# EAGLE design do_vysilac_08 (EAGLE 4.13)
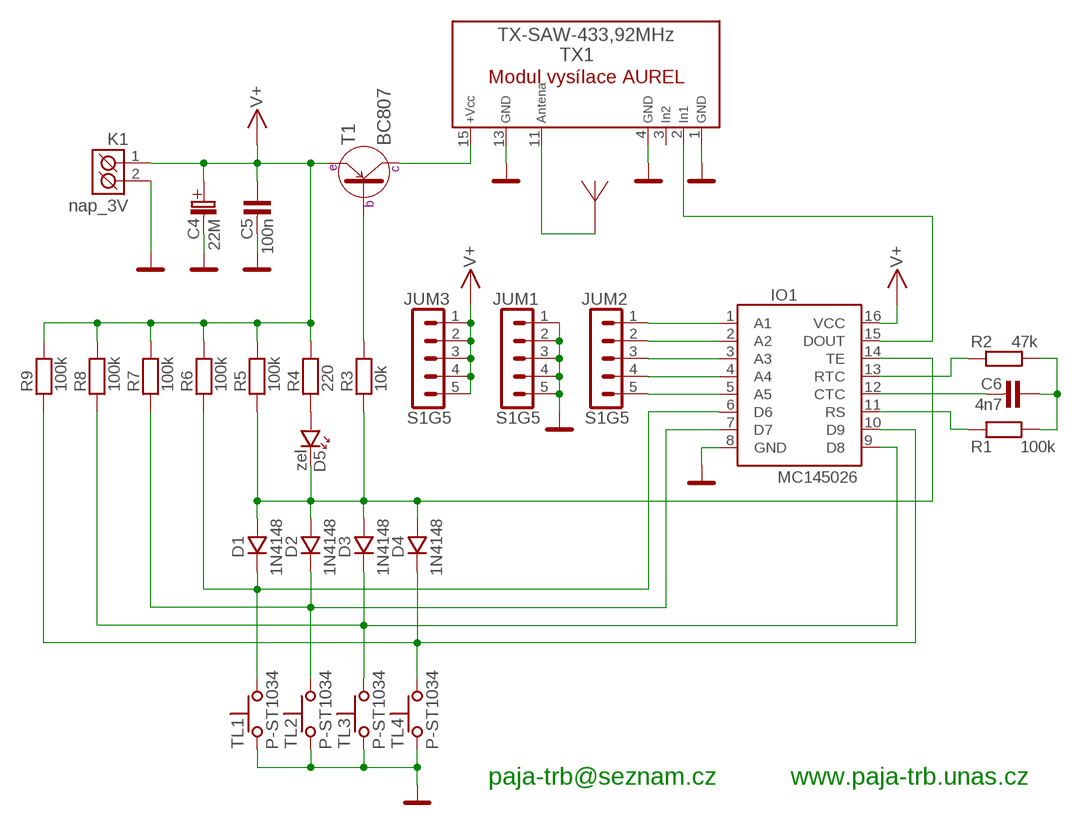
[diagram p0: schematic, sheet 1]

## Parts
ANT1  ANTENA  [PAD_1]
C4  22M  C-ELEKTROLYT_2  [C-EL_2]
C5  100n  C-KERAMIK_SMD_1206  [1206]
C6  4n7  C-KERAMIK_SMD_1206  [1206]
D1  1N4148  1N4148_SMD_SOD80  [SOD-80]
D2  1N4148  1N4148_SMD_SOD80  [SOD-80]
D3  1N4148  1N4148_SMD_SOD80  [SOD-80]
D4  1N4148  1N4148_SMD_SOD80  [SOD-80]
D5  zel  LED_3  [LED_3]
IO1  MC145026  [DIL16]
JUM1  S1G5  S1G5_JUMP  [S1G5_JUM]
JUM2  S1G5  S1G5_JUMP  [S1G5_JUM]
JUM3  S1G5  S1G5_JUMP  [S1G5_JUM]
K1  nap_3V  CZM_5/2  [CZM_5/2]
R1  100k  R_SMD_1206  [1206]
R2  47k  R_SMD_1206  [1206]
R3  10k  R_SMD_1206  [1206]
R4  220  R_SMD_1206  [1206]
R5  100k  R_SMD_1206  [1206]
R6  100k  R_SMD_1206  [1206]
R7  100k  R_SMD_1206  [1206]
R8  100k  R_SMD_1206  [1206]
R9  100k  R_SMD_1206  [1206]
T1  BC807  [SOT-23]
TL1  P-ST1034  [P-ST1034]
TL2  P-ST1034  [P-ST1034]
TL3  P-ST1034  [P-ST1034]
TL4  P-ST1034  [P-ST1034]
TX1  TX-SAW433  [TX-SAW]

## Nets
+3V: C4.C+(C_EL+) C5.1 IO1.16(VCC) JUM3.1 JUM3.2 JUM3.3 JUM3.4 JUM3.5 K1.1(K1) R4.2 R5.2 R6.2 R7.2 R8.2 R9.2 T1.1(E) ; supply symbol labelled V+
GND: C4.C-(C_EL-) C5.2 IO1.8(GND) JUM1.1 JUM1.2 JUM1.3 JUM1.4 JUM1.5 K1.2(K2) TL1.S TL2.S TL3.S TL4.S TX1.1(GND) TX1.4(GND) TX1.13(GND)
N$1: IO1.11(RS) R1.1
N$3: D2.K IO1.7(D7) R7.1 TL2.1
N$4: D5.A R4.1
N$5: IO1.1(A1) JUM2.1
N$6: D1.K IO1.6(D6) R6.1 TL1.1
N$7: D1.A D2.A D3.A D4.A D5.K IO1.14(TE) R3.1 R5.1
N$8: IO1.15(DOUT) TX1.2(IN1)
N$9: IO1.13(RTC) R2.1
N$10: C6.2 IO1.12(CTC)
N$11: C6.1 R1.2 R2.2
N$12: D4.K IO1.10(D9) R9.1 TL4.1
N$13: D3.K IO1.9(D8) R8.1 TL3.1
N$14: R3.2 T1.2(B)
N$15: T1.3(C) TX1.15(VCC)
N$21: IO1.2(A2) JUM2.2
N$22: IO1.3(A3) JUM2.3
N$23: IO1.4(A4) JUM2.4
N$24: IO1.5(A5) JUM2.5
N$25: ANT1.1 TX1.11(ANTENA)
Unconnected: TX1.3(IN2)

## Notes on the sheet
- paja-trb@seznam.cz | www.paja-trb.unas.cz

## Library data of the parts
ANT1 = #PaJa_15:ANTENA: SCH symbol - Anteny + pajeci bod na DPS
C4 = #PaJa_15:C-ELEKTROLYT: Kondenzator - elektrolyticky
C5 C6 = #PaJa_15:C-KERAMIK: Kondenzator - keramicky
D1-D4 = #PaJa_15:1N4148: Univerzalni dioda - 0,15A, 75V
D5 = #PaJa_15:LED: LED - jednobarevna
IO1 = #PaJa_15:MC145026
JUM1-JUM3 = #PaJa_15:S1G5_JUMP: Radove konektory - koliky - 5x
K1 = #PaJa_15:CZM_5/2: Svorkovnice - roztec 5,08mm - dvojita
R1-R9 = #PaJa_15:R: Rezistor
T1 = #PaJa_15:BC807
TL1-TL4 = #PaJa_19:P-ST1034: &micro;-spinac - (10x10mm)
TX1 = #PaJa_15:TX-SAW433

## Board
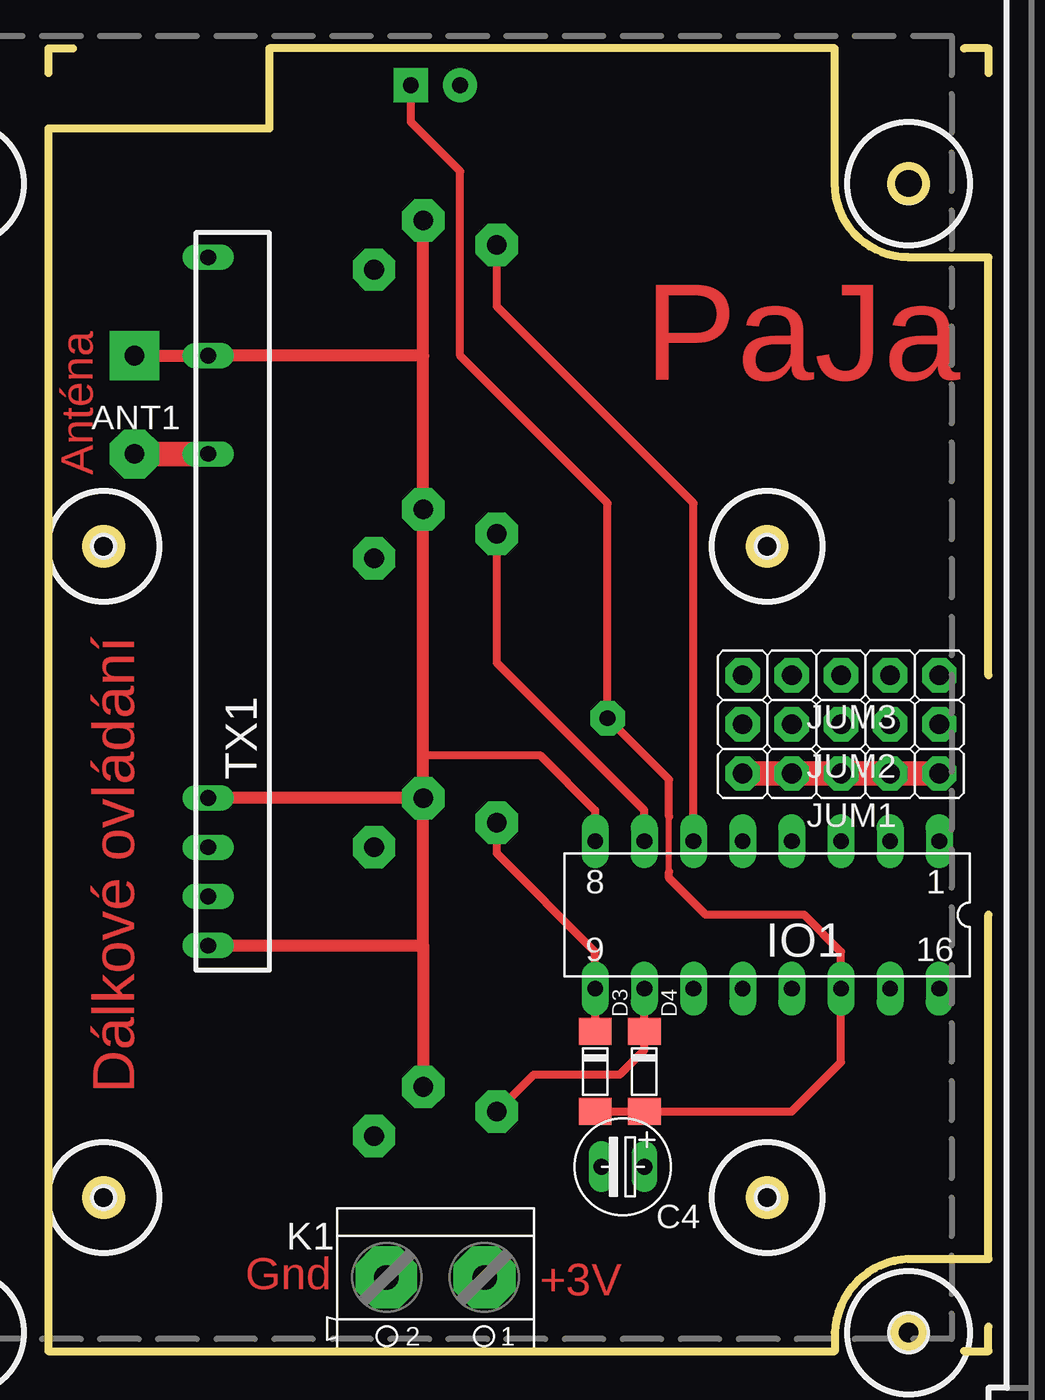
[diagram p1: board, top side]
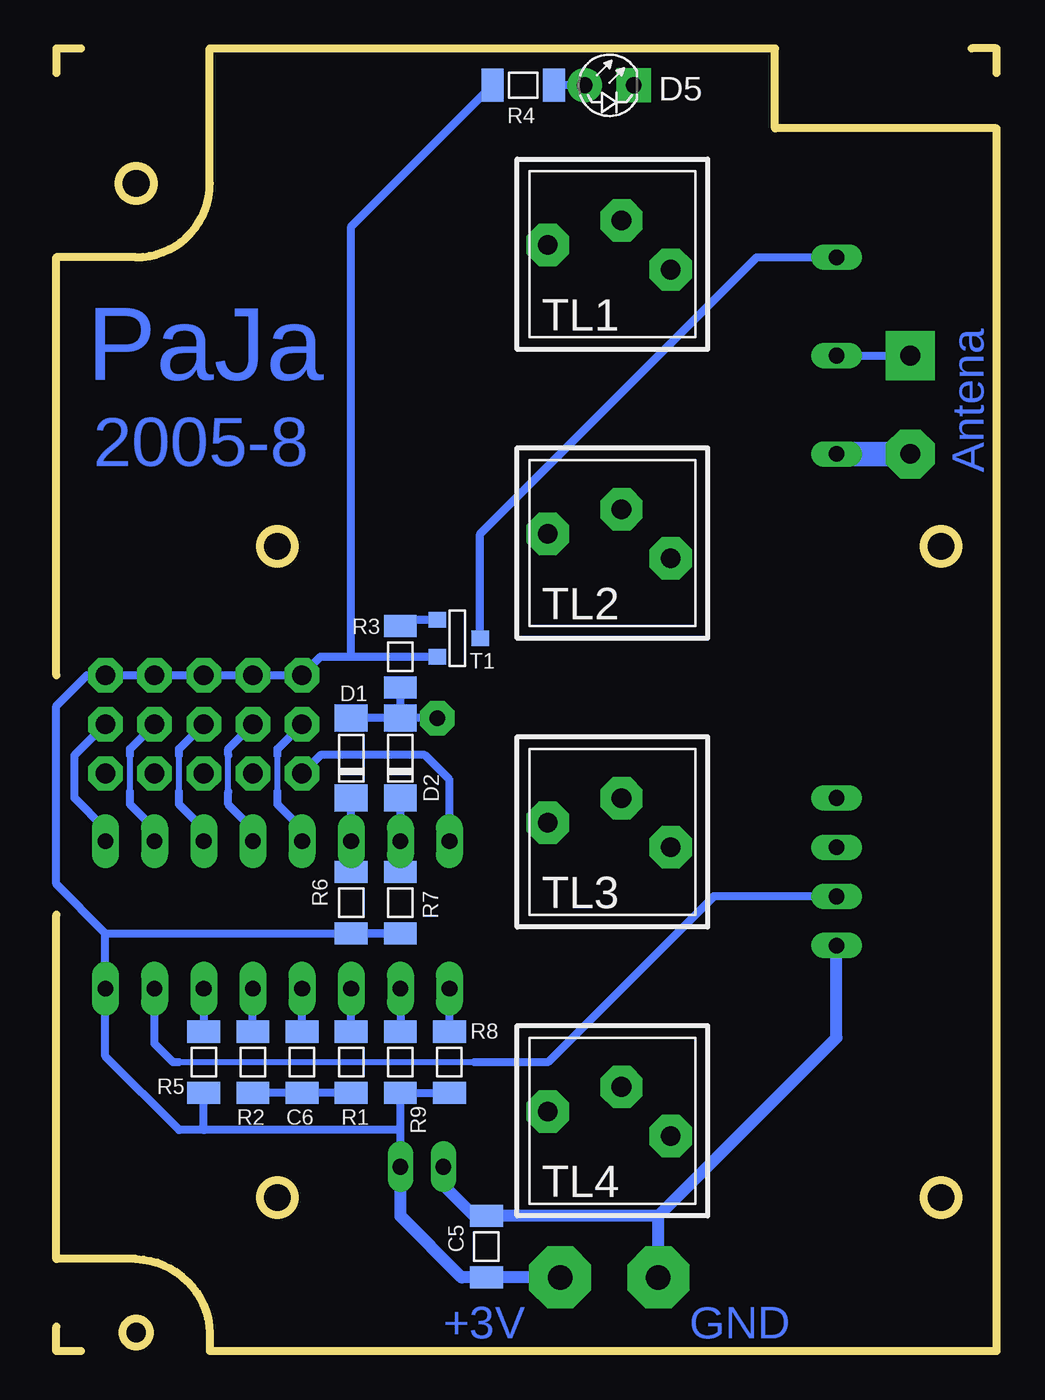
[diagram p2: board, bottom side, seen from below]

Size 48.58 x 67.31 mm. Coordinates in mm from the lower left corner, seen from the top.
Outline: 48.58,34.92 48.58,56.52 44.45,56.52 arc-90 40.64,60.32 40.64,67.31 11.43,67.31 11.43,63.18 0,63.18 0,0 40.64,0 40.64,0.95 arc-85 44.45,4.76 48.58,4.76 48.58,22.54
Outline: 47.31,0 48.58,0 48.58,1.27
Outline: 47.31,67.31 48.58,67.31 48.58,66.04
Outline: 0,66.04 0,67.31 1.27,67.31
Outline: circle at 2.86,7.94 radius 0.9
Outline: circle at 2.86,41.59 radius 0.9
Outline: circle at 37.15,41.59 radius 0.9
Outline: circle at 37.15,7.94 radius 0.9
Outline: circle at 44.45,0.95 radius 0.71
Outline: circle at 44.45,60.32 radius 0.9
Copper layers (1*16): Top 0.035mm / dielectric 1.5mm / Bottom 0.035mm
Design rules "default": minimum track width 10mil, minimum drill 24mil, track to track 8mil, track to pad 8mil, pad to pad 8mil, via to via 8mil, smd to smd 8mil, copper to edge 40mil, drill to drill 8mil, minimum pad ring 10mil, minimum via ring 8mil, stop-mask expansion 4mil, vias tented up to drill 0mil, thermal gap 10mil

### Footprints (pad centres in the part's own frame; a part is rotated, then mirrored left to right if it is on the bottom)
PAD_1 = drill 1.016 pad 2.54 octagon: 1 0,0
C-EL_2 = drill 0.813 pad 1.27 long: C+ 0,0; C- 2.223,0
1206 = smd 1.143 x 1.702: 1 -1.587,0; 2 1.587,0
SOD-80 = smd 1.397 x 1.702: A 1.905,0; K -2.223,0
LED_3 = drill 0.813 pad 1.778 round: A -1.27,0 | drill 0.813 pad 1.778 square: K 1.27,0
DIL16 = drill 0.813 pad 1.4 long: 1 -8.89,-3.81; 2 -6.35,-3.81; 3 -3.81,-3.81; 4 -1.27,-3.81; 5 1.27,-3.81; 6 3.81,-3.81; 7 6.35,-3.81; 8 8.89,-3.81; 9 8.89,3.81; 10 6.35,3.81; 11 3.81,3.81; 12 1.27,3.81; 13 -1.27,3.81; 14 -3.81,3.81; 15 -6.35,3.81; 16 -8.89,3.81
S1G5_JUM = drill 1.016 pad 1.778 octagon: 1 -5.08,0; 2 -2.54,0; 3 0,0; 4 2.54,0; 5 5.08,0
CZM_5/2 = drill 1.27 pad 3.2 octagon: 1 -2.54,0; 2 2.54,0
SOT-23 = smd 0.787 x 0.889: 1 0.953,-0.953; 2 -0.953,-0.953; 3 0,1.27
P-ST1034 = drill 1.016 pad 2.184 octagon: 1 -3.175,0.635; 2 3.175,-0.635; S 0.635,1.905
TX-SAW = drill 0.813 pad 1.27 long: 1 -17.78,0.318; 2 -15.24,0.318; 3 -12.7,0.318; 4 -10.16,0.318; 11 7.62,0.318; 13 12.7,0.318; 15 17.78,0.318

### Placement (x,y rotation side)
ANT1  4.45,46.35 0 top
C4  30.8,9.53 180 top
C5  26.35,5.4 90 bottom
C6  35.88,14.92 90 bottom
D1  33.34,30.8 90 bottom
D2  30.8,30.8 90 bottom
D3  28.26,14.29 270 top
D4  30.8,14.29 270 top
D5  20,65.41 0 bottom
IO1  37.15,22.54 180 top
JUM1  40.96,29.84 180 top
JUM2  40.96,32.38 180 top
JUM3  40.96,34.92 180 top
K1  20,3.81 180 top
R1  33.34,14.92 270 bottom
R2  38.42,14.92 270 bottom
R3  30.8,35.88 90 bottom
R4  24.45,65.41 180 bottom
R5  40.96,14.92 270 bottom
R6  33.34,23.18 270 bottom
R7  30.8,23.18 270 bottom
R8  28.26,14.92 270 bottom
R9  30.8,14.92 270 bottom
T1  27.94,36.83 270 bottom
TL1  20,56.52 0 bottom
TL2  20,41.59 0 bottom
TL3  20,26.67 0 bottom
TL4  20,11.75 0 bottom
TX1  8.57,38.73 90 top
U$1  [U-KP20]  not placed on the board

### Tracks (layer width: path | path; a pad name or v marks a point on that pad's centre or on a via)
+3V
  Bottom 0.406: JUM3.1 JUM3.2 JUM3.3 | JUM3.3 JUM3.4 JUM3.5 34.92,35.88 33.34,35.88 | JUM3.1 JUM3.3 | 33.34,35.88 T1.1 | 33.34,35.88 33.34,58.1 R4.2 | 46.04,21.59 IO1.16 46.04,15.24 42.23,11.43 40.96,11.43 | 46.04,21.59 48.58,24.13 48.58,33.34 46.99,34.92 JUM3.1 | R6.2 R7.2 46.04,21.59 | 30.8,11.43 R9.2 R8.2 | 30.8,11.43 40.96,11.43 | 40.96,11.43 R5.2 | C4.C+ 30.8,11.43
  Bottom 0.61: K1.1 C5.1 27.62,3.81 30.8,6.98 C4.C+
GND  (via drill 1.02 pad 2.54)
  Top 0.406: IO1.8 28.26,27.94 25.4,30.8 19.37,30.8
  Top 0.61: TL3.S 19.37,30.8 TL2.S 19.37,51.43 | 19.37,51.43 TL1.S | 19.37,20.95 TL4.S | 19.37,20.95 TL3.S | 19.37,51.43 TX1.13 v4.45,51.43 | TL3.S TX1.4 | TX1.1 19.37,20.95
  Top 1.27: JUM1.5 JUM1.4 JUM1.3 JUM1.2 JUM1.1
  Bottom 0.406: JUM1.5 34.92,30.8 29.53,30.8 28.26,29.53 IO1.8 | TX1.13 v4.45,51.43
  Bottom 0.61: K1.2 17.46,6.98 | 17.46,6.98 C5.2 26.99,6.98 28.57,8.57 C4.C- | TX1.1 8.26,16.19 17.46,6.98
N$1
  Bottom 0.406: R1.1 IO1.11
N$3
  Top 0.406: IO1.7 30.8,27.94 23.18,35.56 TL2.1
  Bottom 0.406: R7.1 IO1.7 D2.K
N$4
  Bottom 0.406: D5.A R4.1
N$5
  Bottom 0.406: JUM2.1 47.62,30.8 47.62,28.58 46.04,26.99 IO1.1
N$6
  Top 0.406: IO1.6 33.34,43.81 23.18,53.98 TL1.1
  Bottom 0.406: R6.1 IO1.6 D1.K
N$7  (via drill 0.81 pad 1.78)
  Top 0.305: 32.07,24.76 32.07,27.62
  Top 0.406: D3.A D4.A 38.42,12.38 40.96,14.92 IO1.14 40.96,20.64 39.05,22.54 33.97,22.54 32.07,24.45 32.07,24.76 | 32.07,27.62 32.07,29.53 v28.89,32.7 28.89,43.81 21.27,51.43 21.27,60.96 18.73,63.5 D5.K
  Bottom 0.406: IO1.14 R5.1 | D2.A D1.A | v28.89,32.7 D2.A | D2.A R3.1
N$8
  Bottom 0.305: 26.99,14.92 42.23,14.92
  Bottom 0.406: IO1.15 43.5,15.88 42.55,14.92 42.23,14.92 | 26.99,14.92 23.18,14.92 14.6,23.49 TX1.2
N$9
  Bottom 0.406: R2.1 IO1.13
N$10
  Bottom 0.406: C6.2 IO1.12
N$11
  Bottom 0.406: R2.2 C6.1 R1.2
N$12
  Top 0.406: IO1.10 R9.1 30.8,15.56 29.53,14.29 25.08,14.29 TL4.1
  Bottom 0.406: IO1.10 R9.1
N$13
  Top 0.406: R8.1 IO1.9 28.26,20.64 23.18,25.72 TL3.1
  Bottom 0.406: R8.1 IO1.9
N$14
  Bottom 0.406: T1.2 30.48,37.78 R3.2
N$15
  Bottom 0.406: T1.3 26.67,42.23 12.38,56.52 TX1.15
N$21
  Bottom 0.305: 44.77,28.89 44.77,30.8
  Bottom 0.406: IO1.2 43.5,26.99 44.77,28.26 44.77,28.89 | JUM2.2 44.77,31.11 44.77,30.8
N$22
  Bottom 0.305: 42.23,28.89 42.23,30.8
  Bottom 0.406: IO1.3 40.96,26.99 42.23,28.26 42.23,28.89 | JUM2.3 42.23,31.11 42.23,30.8
N$23
  Bottom 0.305: 39.69,28.89 39.69,30.8
  Bottom 0.406: IO1.4 38.42,26.99 39.69,28.26 39.69,28.89 | JUM2.4 39.69,31.11 39.69,30.8
N$24
  Bottom 0.305: 37.15,28.89 37.15,30.8
  Bottom 0.406: IO1.5 35.88,26.99 37.15,28.26 37.15,28.89 | JUM2.5 37.15,31.11 37.15,30.8
N$25
  Top 1.27: ANT1.1 TX1.11
  Bottom 1.27: ANT1.1 TX1.11

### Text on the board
Top: Anténa | PaJa | Dálkové ovládání | Gnd | +3V
Bottom: PaJa | 2005-8 | Antena | GND | +3V
Zapojeni: 433,92MHz | Vysílá | 2008 | Off On | Dálkové ovládání | PaJa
